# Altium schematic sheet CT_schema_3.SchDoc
size 276 x 169 mm
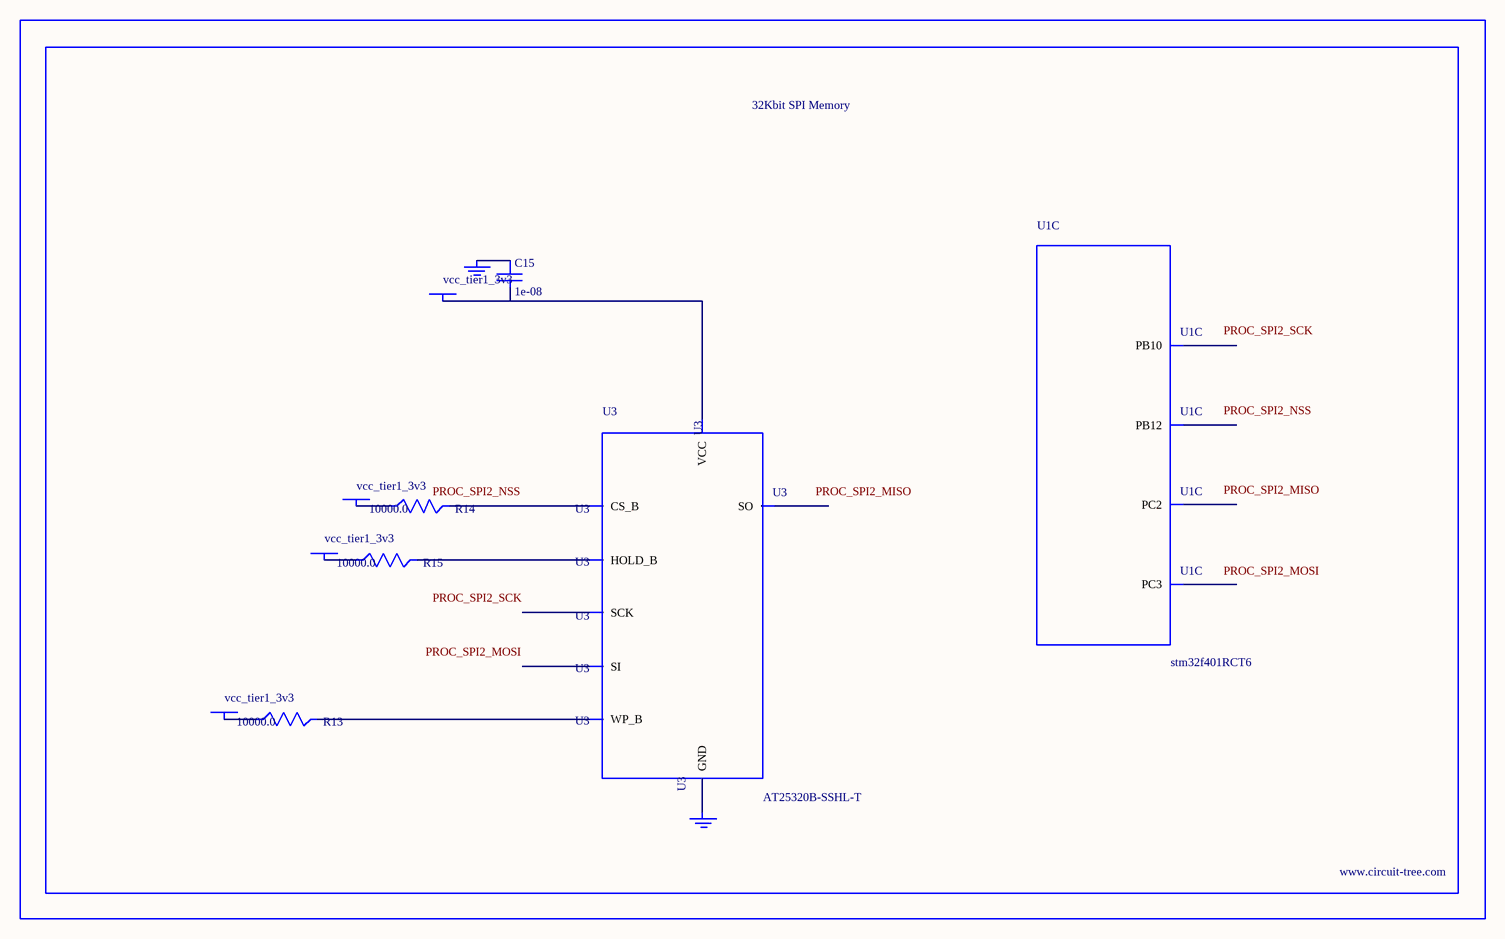
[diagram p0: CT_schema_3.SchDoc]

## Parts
BORDER2  (no value)
C15  1e-08  [C0402]
GND_INSTANCE_2_0  (no value)
GND_INSTANCE_2_1  (no value)
POWER_INSTANCE_2_0  vcc_tier1_3v3
POWER_INSTANCE_2_1  vcc_tier1_3v3
POWER_INSTANCE_2_2  vcc_tier1_3v3
POWER_INSTANCE_2_3  vcc_tier1_3v3
R13  10000.0  [R0603]
R14  10000.0  [R0603]
R15  10000.0  [R0603]
U1  stm32f401RCT6  [LQFP64]  (part C of 9)
U3  AT25320B-SSHL-T  [SOIC-8]

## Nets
NetC15_1: C15.1 GND_INSTANCE_2_0.0(GND)
NetC15_2: C15.2 POWER_INSTANCE_2_3.0(PWR) U3.8(VCC)
NetGND_INSTANCE_2_1_0: GND_INSTANCE_2_1.0(GND) U3.4(GND)
NetPOWER_INSTANCE_2_0_0: POWER_INSTANCE_2_0.0(PWR) R14.1
NetPOWER_INSTANCE_2_1_0: POWER_INSTANCE_2_1.0(PWR) R13.1
NetPOWER_INSTANCE_2_2_0: POWER_INSTANCE_2_2.0(PWR) R15.1
NetR13_2: R13.2 U3.3(WP_B)
NetR14_2: R14.2 U3.1(CS_B)
NetR15_2: R15.2 U3.7(HOLD_B)

Not connected (* = marked no-connect by the designer): U1 10(PC2) 11(PC3) 29(PB10) 33(PB12); U3 2(SO) 5(SI) 6(SCK)

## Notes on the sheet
- Labels drawn without touching a wire or pin: PROC_SPI2_MISO, PROC_SPI2_MOSI, PROC_SPI2_NSS, PROC_SPI2_SCK

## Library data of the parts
BORDER2 = BORDER_PAGE2
C15 = C0402C103K3RAC
GND_INSTANCE_2_0 GND_INSTANCE_2_1 = GND
POWER_INSTANCE_2_0-POWER_INSTANCE_2_3 = PWR
R13-R15 = RC0603JR-0710KL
